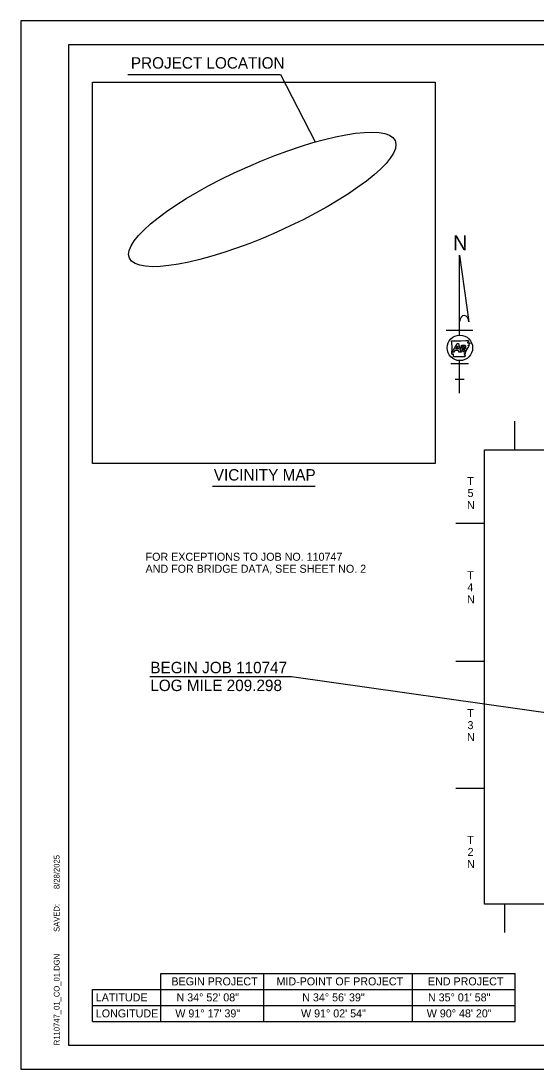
# Model space of a CAD drawing. Extents: x -0.96 to 2.36, y -0.12 to 0.92.
# Drawn here: x 0 to 0.451, y 0 to 0.917 of the extents above; entities that cross this region are included whole.
import ezdxf

# ---------------------------------------------------------------- set-up
doc = ezdxf.new("R2010")
doc.units = 0
for name, color, linetype in [('DSN_DRFT_DNC', 7, 'Continuous'), ('Level 41', 7, 'Continuous'), ('Level 46', 7, 'Continuous'), ('Level 49', 7, 'Continuous'), ('SHET_Annotations', 7, 'Continuous'), ('SHET_Border-Lines', 7, 'Continuous'), ('SHET_Border-Text', 7, 'Continuous')]:
    doc.layers.add(name, color=color, linetype=linetype)

msp = doc.modelspace()

# ---------------------------------------------------------------- linework, layer by layer
at = {"layer": 'DSN_DRFT_DNC'}
for points in [[(0.0625, 0.863), (0.3625, 0.863), (0.3625, 0.52967), (0.0625, 0.52967)], [(0.4056, 0.54167), (1.05273, 0.54167), (1.05273, 0.1443), (0.4056, 0.1443)]]:
    msp.add_lwpolyline(points, close=True, dxfattribs=at)
at = {"layer": 'Level 41'}
for points in [[(0.0625, 0.863), (0.3625, 0.863), (0.3625, 0.52967), (0.0625, 0.52967)], [(0.4056, 0.54158), (1.05273, 0.54158), (1.05273, 0.14421), (0.4056, 0.14421)]]:
    msp.add_lwpolyline(points, close=True, dxfattribs=at)
at = {"layer": 'Level 46'}
msp.add_line((0.4056, 0.27083), (0.4056, 0.27113), dxfattribs=at)
at = {"layer": 'Level 49'}
msp.add_ellipse((0.21115, 0.76057), major_axis=(0.11625, 0.0514), ratio=0.246348, dxfattribs=at)
at = {"layer": 'SHET_Annotations'}
for p, q in [((0.43174, 0.56667), (0.43175, 0.54167)), ((0.3806, 0.47729), (0.4056, 0.47729)), ((0.3806, 0.35664), (0.4056, 0.35664)), ((0.1129, 0.34331), (0.23672, 0.34331)), ((0.23672, 0.34331), (0.50486, 0.30548)), ((0.3806, 0.24574), (0.4056, 0.24574)), ((0.42306, 0.1443), (0.42306, 0.1193))]:
    msp.add_line(p, q, dxfattribs=at)
at = {"layer": 'SHET_Border-Lines'}
for points in [[(0, 0), (1.41666, 0), (1.41666, 0.91666), (0, 0.91666)], [(0.04167, 0.02083), (1.39583, 0.02083), (1.39583, 0.89583), (0.04167, 0.89583)]]:
    msp.add_lwpolyline(points, close=True, dxfattribs=at)
at = {"layer": 'SHET_Border-Text'}
for p, q in [((0.09358, 0.86996), (0.22715, 0.86996)), ((0.22715, 0.86996), (0.25754, 0.81085)), ((0.38384, 0.71178), (0.3919, 0.65353)), ((0.38384, 0.64193), (0.38384, 0.71178)), ((0.37218, 0.64625), (0.39551, 0.64625)), ((0.37731, 0.62695), (0.38162, 0.63455)), ((0.38162, 0.63455), (0.3829, 0.63455)), ((0.3855, 0.63297), (0.38849, 0.63297)), ((0.37879, 0.62695), (0.37731, 0.62695)), ((0.3797, 0.62854), (0.37879, 0.62695)), ((0.38272, 0.62854), (0.3797, 0.62854)), ((0.38048, 0.62993), (0.38189, 0.63242)), ((0.38242, 0.62993), (0.38048, 0.62993)), ((0.38557, 0.62695), (0.38306, 0.62695)), ((0.38651, 0.62937), (0.38599, 0.62937)), ((0.38743, 0.63027), (0.38615, 0.63027)), ((0.38643, 0.63189), (0.38784, 0.63189)), ((0.3874, 0.62695), (0.38651, 0.62937)), ((0.38872, 0.62695), (0.3874, 0.62695)), ((0.38777, 0.6295), (0.38872, 0.62695)), ((0.3878, 0.62943), (0.38789, 0.62953)), ((0.37607, 0.61718), (0.39162, 0.61718)), ((0.38384, 0.59124), (0.38384, 0.61958)), ((0.37995, 0.60337), (0.38773, 0.60337)), ((0.1675, 0.50967), (0.2575, 0.50967)), ((0.1225, 0.04167), (0.1225, 0.08367)), ((0.1225, 0.08367), (0.4325, 0.08367)), ((0.2125, 0.04167), (0.2125, 0.08367)), ((0.3425, 0.04167), (0.3425, 0.08367)), ((0.4325, 0.04167), (0.4325, 0.08367)), ((0.0625, 0.04167), (0.0625, 0.06967)), ((0.0625, 0.06967), (0.4325, 0.06967)), ((0.0625, 0.05567), (0.4325, 0.05567)), ((0.0625, 0.04167), (0.4325, 0.04167))]:
    msp.add_line(p, q, dxfattribs=at)
for points in [[(0.37675, 0.63702), (0.38101, 0.63702), (0.38475, 0.63703), (0.38916, 0.63709), (0.39121, 0.63714)], [(0.37723, 0.6304), (0.3773, 0.63264), (0.37675, 0.63702)], [(0.3829, 0.63455), (0.38449, 0.62715), (0.3855, 0.63297)], [(0.39057, 0.63509), (0.39257, 0.63519)], [(0.37706, 0.6255), (0.37723, 0.6304)], [(0.38818, 0.62292), (0.37853, 0.62294), (0.37852, 0.62507)], [(0.38189, 0.63242), (0.38242, 0.62993)], [(0.38306, 0.62695), (0.38272, 0.62854)], [(0.38599, 0.62937), (0.38557, 0.62695)], [(0.38615, 0.63027), (0.38643, 0.63189)]]:
    msp.add_lwpolyline(points, dxfattribs=at)
for centre, major_axis, ratio, start_param, end_param in [((0.38787, 0.6534), (-0.00017, 0.0056), 0.719778, 4.712385, 7.768526), ((0.38738, 0.63139), (-0.00193, 0), 0.999987, 1.777838, 4.099264), ((0.38712, 0.63121), (-0.000988, 0), 0.999987, 1.887169, 3.90762)]:
    msp.add_ellipse(centre, major_axis=major_axis, ratio=ratio, start_param=start_param, end_param=end_param, dxfattribs=at)
msp.add_ellipse((0.38403, 0.63076), major_axis=(0.01117, 0), ratio=0.999976, dxfattribs=at)
for points in [[(0.39154, 0.63265), (0.39155, 0.63258), (0.39151, 0.63249), (0.39149, 0.63241), (0.3915, 0.63233), (0.39141, 0.63228), (0.39134, 0.63223), (0.39138, 0.63217), (0.39146, 0.63211), (0.39154, 0.63207), (0.39159, 0.63202), (0.3916, 0.63191), (0.39162, 0.63184), (0.39164, 0.63175), (0.39165, 0.63168), (0.39161, 0.63161), (0.39155, 0.63159), (0.39149, 0.63161), (0.39143, 0.63161), (0.39137, 0.63156), (0.39133, 0.63149), (0.39129, 0.63141), (0.39126, 0.63135), (0.39123, 0.63128), (0.39118, 0.6312), (0.3911, 0.63119), (0.39102, 0.63117), (0.39097, 0.63111), (0.39098, 0.63101), (0.39103, 0.63095), (0.39106, 0.63087), (0.39109, 0.63079), (0.39108, 0.6307), (0.39104, 0.63064), (0.39099, 0.6306), (0.39097, 0.63052), (0.39093, 0.63045), (0.3909, 0.63043), (0.39084, 0.63044), (0.39077, 0.63045), (0.39071, 0.63044), (0.39066, 0.63042), (0.3906, 0.63043), (0.39055, 0.6305), (0.3905, 0.63054), (0.39044, 0.63056), (0.39039, 0.63053), (0.39038, 0.63045), (0.39041, 0.63036), (0.39043, 0.63024), (0.39041, 0.63016), (0.3904, 0.63004)], [(0.39121, 0.63714), (0.39122, 0.63703), (0.39126, 0.63697), (0.39126, 0.63685), (0.39131, 0.63681), (0.39138, 0.63676), (0.39145, 0.63668), (0.39147, 0.6366), (0.39145, 0.6365), (0.39144, 0.6364), (0.39143, 0.63631), (0.39141, 0.63623), (0.39135, 0.63616), (0.39129, 0.63612), (0.39124, 0.63606), (0.3912, 0.636), (0.39113, 0.63594), (0.39106, 0.63587), (0.391, 0.63581), (0.39095, 0.63574), (0.39092, 0.63566), (0.39086, 0.6356), (0.39081, 0.63555), (0.39075, 0.63548), (0.39072, 0.63541), (0.39066, 0.63532), (0.39065, 0.63525), (0.39061, 0.63518), (0.3906, 0.63517)], [(0.39254, 0.63519), (0.39257, 0.63519), (0.39266, 0.63509), (0.3927, 0.63501), (0.39276, 0.63497), (0.39283, 0.63495), (0.39288, 0.63488), (0.39291, 0.63482), (0.39289, 0.63476), (0.39282, 0.63476), (0.39274, 0.63474), (0.39266, 0.63475), (0.39259, 0.63469), (0.39265, 0.63462), (0.39273, 0.63455), (0.39275, 0.63448), (0.39271, 0.63442), (0.39262, 0.63438), (0.39254, 0.63435), (0.39247, 0.63428), (0.39243, 0.63422), (0.39235, 0.6342), (0.39227, 0.63417), (0.39219, 0.63417), (0.39211, 0.63415), (0.39203, 0.63411), (0.39199, 0.63404), (0.39201, 0.63395), (0.392, 0.63384), (0.39209, 0.63381), (0.39216, 0.6338), (0.39224, 0.63377), (0.39223, 0.63371), (0.39218, 0.63363), (0.39211, 0.63358), (0.39204, 0.63355), (0.39198, 0.63349), (0.39201, 0.63343), (0.39206, 0.6334), (0.3921, 0.63334), (0.39209, 0.63328), (0.39203, 0.63324), (0.39196, 0.63326), (0.39191, 0.63333), (0.39185, 0.63335), (0.3918, 0.63337), (0.39175, 0.63334), (0.39175, 0.63326), (0.39173, 0.63318), (0.39174, 0.63312), (0.39177, 0.63303), (0.39176, 0.63297), (0.39174, 0.63288), (0.3917, 0.63279), (0.39165, 0.63276), (0.39162, 0.63286), (0.39162, 0.63294), (0.39158, 0.63299), (0.39154, 0.63299), (0.39149, 0.63295), (0.39143, 0.63289), (0.39135, 0.63282), (0.3913, 0.63276), (0.39133, 0.63268), (0.39139, 0.63266), (0.39143, 0.63267), (0.39145, 0.63272), (0.3915, 0.63273), (0.39154, 0.63265)], [(0.37852, 0.62507), (0.37853, 0.62507), (0.37848, 0.6251), (0.37841, 0.62514), (0.37834, 0.62514), (0.37824, 0.62515), (0.37816, 0.62516), (0.37807, 0.62522), (0.37798, 0.62516), (0.37788, 0.62512), (0.37783, 0.62517), (0.37775, 0.62513), (0.3777, 0.62515), (0.3776, 0.62509), (0.37752, 0.62511), (0.37745, 0.62509), (0.37738, 0.62509), (0.37736, 0.62518), (0.37728, 0.6252), (0.37722, 0.62523), (0.37717, 0.62532), (0.37714, 0.6254), (0.37706, 0.6255)], [(0.38858, 0.62656), (0.38856, 0.62649), (0.38853, 0.62639), (0.38854, 0.6263), (0.38858, 0.62622), (0.38864, 0.62618), (0.38871, 0.62612), (0.3887, 0.62603), (0.38866, 0.626), (0.38857, 0.62602), (0.3885, 0.62605), (0.38844, 0.62603), (0.38836, 0.62599), (0.3883, 0.62598), (0.3883, 0.62586), (0.38838, 0.62577), (0.38845, 0.62577), (0.38853, 0.62576), (0.38856, 0.62566), (0.38851, 0.62558), (0.38844, 0.62554), (0.38834, 0.62559), (0.38826, 0.62564), (0.38819, 0.62569), (0.3881, 0.62571), (0.38805, 0.6257), (0.38803, 0.62559), (0.38807, 0.62549), (0.38814, 0.62542), (0.3882, 0.62533), (0.38819, 0.62527), (0.38815, 0.62525), (0.38806, 0.62523), (0.38801, 0.6252), (0.388, 0.62518), (0.38802, 0.62509), (0.38805, 0.625), (0.38805, 0.62492), (0.38802, 0.62486), (0.38797, 0.62475), (0.38798, 0.62468), (0.38801, 0.62465), (0.38805, 0.62466), (0.3881, 0.6247), (0.38814, 0.62474), (0.38817, 0.62479), (0.38822, 0.62484), (0.38829, 0.6248), (0.38831, 0.62471), (0.38827, 0.62464), (0.38821, 0.62461), (0.38814, 0.62458), (0.38809, 0.62453), (0.38811, 0.62446), (0.38815, 0.62442), (0.38824, 0.62444), (0.38831, 0.62447), (0.38835, 0.6245), (0.38839, 0.62455), (0.38841, 0.6246), (0.38845, 0.62464), (0.38851, 0.62466), (0.38854, 0.62462), (0.38853, 0.62453), (0.38849, 0.62444), (0.38844, 0.62437), (0.38839, 0.62432), (0.38832, 0.62421), (0.38833, 0.62411), (0.38836, 0.62403), (0.38839, 0.62397), (0.38846, 0.62398), (0.38853, 0.62399), (0.38857, 0.62396), (0.38856, 0.62388), (0.38851, 0.62381), (0.38846, 0.62374), (0.38844, 0.62365), (0.38845, 0.62358), (0.38845, 0.62352), (0.38843, 0.62345), (0.38839, 0.62342), (0.38829, 0.62342), (0.38819, 0.62343), (0.38813, 0.6234), (0.38814, 0.62331), (0.3882, 0.62324), (0.38824, 0.62321), (0.38831, 0.62314), (0.38833, 0.62308), (0.38832, 0.62302), (0.38829, 0.62298), (0.38818, 0.62292)], [(0.38858, 0.62656), (0.38856, 0.62649), (0.38853, 0.62639), (0.38854, 0.6263), (0.38858, 0.62622), (0.38864, 0.62618), (0.38871, 0.62612), (0.3887, 0.62603), (0.38866, 0.626), (0.38857, 0.62602), (0.3885, 0.62605), (0.38844, 0.62603), (0.38836, 0.62599), (0.3883, 0.62598), (0.3883, 0.62586), (0.38838, 0.62577), (0.38845, 0.62577), (0.38853, 0.62576), (0.38856, 0.62566), (0.38851, 0.62558), (0.38844, 0.62554), (0.38834, 0.62559), (0.38826, 0.62564), (0.38819, 0.62569), (0.3881, 0.62571), (0.38805, 0.6257), (0.38803, 0.62559), (0.38807, 0.62549), (0.38814, 0.62542), (0.3882, 0.62533), (0.38819, 0.62527), (0.38815, 0.62525), (0.38806, 0.62523), (0.38801, 0.6252), (0.388, 0.62518), (0.38802, 0.62509), (0.38805, 0.625), (0.38805, 0.62492), (0.38802, 0.62486), (0.38797, 0.62475), (0.38798, 0.62468), (0.38801, 0.62465), (0.38805, 0.62466), (0.3881, 0.6247), (0.38814, 0.62474), (0.38817, 0.62479), (0.38822, 0.62484), (0.38829, 0.6248), (0.38831, 0.62471), (0.38827, 0.62464), (0.38821, 0.62461), (0.38814, 0.62458), (0.38809, 0.62453), (0.38811, 0.62446), (0.38815, 0.62442), (0.38824, 0.62444), (0.38831, 0.62447), (0.38835, 0.6245), (0.38839, 0.62455), (0.38841, 0.6246), (0.38845, 0.62464), (0.38851, 0.62466), (0.38854, 0.62462), (0.38853, 0.62453), (0.38849, 0.62444), (0.38844, 0.62437), (0.38839, 0.62432), (0.38832, 0.62421), (0.38833, 0.62411), (0.38836, 0.62403), (0.38839, 0.62397), (0.38846, 0.62398), (0.38853, 0.62399), (0.38857, 0.62396), (0.38856, 0.62388), (0.38851, 0.62381), (0.38846, 0.62374), (0.38844, 0.62365), (0.38845, 0.62358), (0.38845, 0.62352), (0.38843, 0.62345), (0.38839, 0.62342), (0.38829, 0.62342), (0.38819, 0.62343), (0.38813, 0.6234), (0.38814, 0.62331), (0.3882, 0.62324), (0.38824, 0.62321), (0.38831, 0.62314), (0.38833, 0.62308), (0.38832, 0.62302), (0.38829, 0.62298), (0.38818, 0.62292)], [(0.38894, 0.62755), (0.38893, 0.62754), (0.38888, 0.62748), (0.38891, 0.62739), (0.38901, 0.62735), (0.38906, 0.62727), (0.38906, 0.62719), (0.38903, 0.62708), (0.38898, 0.62703), (0.38889, 0.62701), (0.38882, 0.62699), (0.38881, 0.62687), (0.38878, 0.62681), (0.38872, 0.62679), (0.38864, 0.62683), (0.38859, 0.62685), (0.38854, 0.62688), (0.38846, 0.62692), (0.38841, 0.62691), (0.38842, 0.6268), (0.38843, 0.62679), (0.38849, 0.62671), (0.38855, 0.62664), (0.38858, 0.62656)], [(0.38894, 0.62755), (0.38893, 0.62754), (0.38888, 0.62748), (0.38891, 0.62739), (0.38901, 0.62735), (0.38906, 0.62727), (0.38906, 0.62719), (0.38903, 0.62708), (0.38898, 0.62703), (0.38889, 0.62701), (0.38882, 0.62699), (0.38881, 0.62687), (0.38878, 0.62681), (0.38872, 0.62679), (0.38864, 0.62683), (0.38859, 0.62685), (0.38854, 0.62688), (0.38846, 0.62692), (0.38841, 0.62691), (0.38842, 0.6268), (0.38843, 0.62679), (0.38849, 0.62671), (0.38855, 0.62664), (0.38858, 0.62656)], [(0.3904, 0.63004), (0.39031, 0.62997), (0.39026, 0.6299), (0.39003, 0.62992), (0.39004, 0.62984), (0.38995, 0.62979), (0.38988, 0.62974), (0.38992, 0.62968), (0.39, 0.62962), (0.39008, 0.62957), (0.39013, 0.62953), (0.39014, 0.62942), (0.39016, 0.62935), (0.39018, 0.62926), (0.39019, 0.62919), (0.39015, 0.62911), (0.39009, 0.6291), (0.39003, 0.62912), (0.38996, 0.62912), (0.38991, 0.62907), (0.38987, 0.62899), (0.38983, 0.62892), (0.3898, 0.62886), (0.38977, 0.62879), (0.38971, 0.62871), (0.38964, 0.6287), (0.38956, 0.62868), (0.38951, 0.62862), (0.38952, 0.62852), (0.38956, 0.62845), (0.3896, 0.62837), (0.38963, 0.6283), (0.38961, 0.62821), (0.38958, 0.62814), (0.38953, 0.6281), (0.38951, 0.62802), (0.38947, 0.62796), (0.38944, 0.62794), (0.38938, 0.62794), (0.38931, 0.62796), (0.38925, 0.62795), (0.3892, 0.62792), (0.38914, 0.62794), (0.38908, 0.628), (0.38904, 0.62805), (0.38898, 0.62807), (0.38893, 0.62804), (0.38892, 0.62795), (0.38895, 0.62786), (0.38897, 0.62774), (0.38895, 0.62767), (0.38894, 0.62755)]]:
    msp.add_spline(points, degree=3, dxfattribs=at)

# ---------------------------------------------------------------- texts
at = {"layer": 'SHET_Annotations'}
for s, height, p in [('PROJECT LOCATION', 0.01, (0.09618, 0.87496)), ('VICINITY MAP', 0.01, (0.16874, 0.51467)), ('T', 0.007, (0.39046, 0.51079)), ('5', 0.007, (0.39074, 0.50029)), ('N', 0.007, (0.39031, 0.48979)), ('FOR EXCEPTIONS TO JOB NO. 110747 ', 0.007, (0.10905, 0.44455)), ('AND FOR BRIDGE DATA, SEE SHEET NO. 2', 0.007, (0.10905, 0.43405)), ('T', 0.007, (0.39046, 0.42842)), ('4', 0.007, (0.39061, 0.41792)), ('N', 0.007, (0.39031, 0.40742)), ('T', 0.007, (0.39046, 0.30778)), ('3', 0.007, (0.39071, 0.29728)), ('N', 0.007, (0.39031, 0.28678)), ('T', 0.007, (0.39046, 0.19688)), ('2', 0.007, (0.3908, 0.18638)), ('N', 0.007, (0.39031, 0.17588)), ('N 34° 52\' 08"', 0.007, (0.13612, 0.05917)), ('N 34° 56\' 39"', 0.007, (0.24612, 0.05917)), ('N 35° 01\' 58"', 0.007, (0.35612, 0.05917)), ('W 91° 17\' 39"', 0.007, (0.13506, 0.04517)), ('W 91° 02\' 54"', 0.007, (0.24506, 0.04517)), ('W 90° 48\' 20"', 0.007, (0.35506, 0.04517))]:
    msp.add_text(s, height=height, dxfattribs=at).set_placement(p)
at = {"layer": 'SHET_Border-Text'}
for s, height, p in [('N', 0.013, (0.37805, 0.71617)), ('STS 10-03-17', 0.000323, (0.38296, 0.61967)), ('BEGIN JOB 110747', 0.01, (0.1132, 0.34616)), ('LOG MILE 209.298', 0.01, (0.11315, 0.33056)), ('BEGIN PROJECT', 0.007, (0.13165, 0.07317)), ('MID-POINT OF PROJECT', 0.007, (0.2236, 0.07317)), ('END PROJECT', 0.007, (0.3561, 0.07317)), ('LATITUDE', 0.007, (0.0655, 0.05917)), ('LONGITUDE', 0.007, (0.0655, 0.04517))]:
    msp.add_text(s, height=height, dxfattribs=at).set_placement(p)
for s, p in [('8/28/2025', (0.03375, 0.15743)), ('     SAVED: ', (0.03375, 0.11064)), ('R110747_01_CO_01.DGN', (0.03375, 0.02083))]:
    msp.add_text(s, height=0.005, rotation=90, dxfattribs=at).set_placement(p)

doc.saveas('drawing.dxf')
